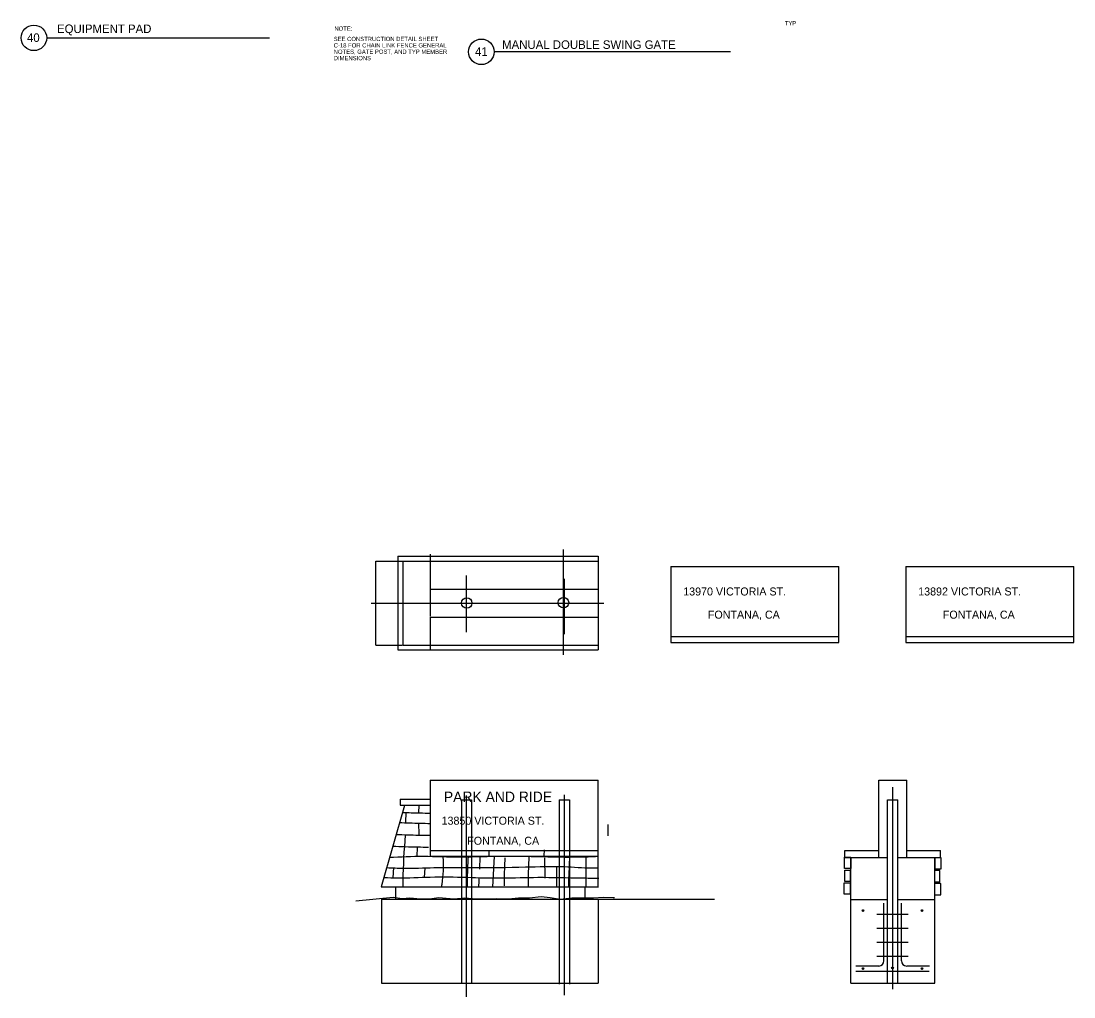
# Model space of a CAD drawing. Extents: x -121875 to -117742, y -103854 to -101122.
# Drawn here: x -121845 to -120364, y -103854 to -102481 of the extents above; entities that cross this region are included whole.
import ezdxf

# ---------------------------------------------------------------- set-up
doc = ezdxf.new("R2010")
doc.units = 0
doc.layers.add('49 Planting', color=7, linetype='Continuous')
doc.layers.add('Misc CnstDet(22)', color=7, linetype='Continuous')

msp = doc.modelspace()

# ---------------------------------------------------------------- linework, layer by layer
at = {"layer": '49 Planting'}
for p, q in [((-121081.8, -103372.5), (-121081.8, -103224.1)), ((-121346, -103358.7), (-121346, -103240.5)), ((-121346, -103240.5), (-121308.4, -103240.5)), ((-121315.3, -103233.6), (-121033.2, -103233.6)), ((-121315.3, -103233.6), (-121315.3, -103365.5)), ((-121307.9, -103240.5), (-121307.9, -103358.7)), ((-121307.9, -103240.5), (-121269.3, -103240.5)), ((-121269.6, -103231.1), (-121269.6, -103279.2)), ((-121269.6, -103234), (-121269.6, -103239.9)), ((-121269.3, -103240.5), (-121032.9, -103240.5)), ((-121033.2, -103233.6), (-121033.2, -103365.5)), ((-120930.9, -103248.1), (-120930.9, -103355)), ((-120930.9, -103248.1), (-120694.5, -103248.1)), ((-120694.5, -103355), (-120694.5, -103248.1)), ((-120600.2, -103248.1), (-120600.2, -103355)), ((-120600.2, -103248.1), (-120363.8, -103248.1)), ((-120363.8, -103355), (-120363.8, -103248.1)), ((-121218.9, -103261.1), (-121218.9, -103340.6)), ((-121081, -103265.6), (-121081, -103343.4)), ((-121270, -103279.9), (-121033.3, -103279.9)), ((-121269.6, -103279.8), (-121269.6, -103317.9)), ((-121352.9, -103299.6), (-121025, -103299.6)), ((-121269.6, -103319.1), (-121269.6, -103359)), ((-121269.3, -103319.3), (-121033.7, -103319.3)), ((-121346, -103358.7), (-121308.9, -103358.7)), ((-121307.9, -103358.7), (-121269.6, -103358.7)), ((-121269.6, -103358.7), (-121033.8, -103358.7)), ((-121269.6, -103359), (-121269.6, -103365.5)), ((-120930.9, -103346.9), (-120930.9, -103355)), ((-120930.9, -103346.9), (-120694.3, -103346.9)), ((-120930.9, -103355), (-120694.5, -103355)), ((-120600.2, -103346.9), (-120600.2, -103355)), ((-120600.2, -103346.9), (-120363.6, -103346.9)), ((-120600.2, -103355), (-120363.8, -103355)), ((-121315.3, -103365.5), (-121033.2, -103365.5)), ((-121269.6, -103548.9), (-121269.6, -103655.8)), ((-121269.6, -103548.9), (-121033.2, -103548.9)), ((-121033.2, -103698.7), (-121033.2, -103548.9)), ((-120638.4, -103657.3), (-120638.4, -103548.9)), ((-120638.4, -103548.9), (-120599, -103548.9)), ((-120599, -103657), (-120599, -103548.9)), ((-120618.7, -103843), (-120618.7, -103558.6)), ((-121312, -103575.5), (-121270.2, -103575.5)), ((-121312, -103575.5), (-121312, -103584.2)), ((-121225.7, -103576.6), (-121225.7, -103833.9)), ((-121225.7, -103576.6), (-121211.5, -103576.6)), ((-121218.9, -103570.6), (-121218.9, -103853.8)), ((-121211.5, -103576.6), (-121211.5, -103834.8)), ((-121087.9, -103576.6), (-121087.9, -103835.7)), ((-121087.9, -103576.6), (-121073.7, -103576.6)), ((-121081, -103569.7), (-121081, -103851.1)), ((-121073.7, -103576.6), (-121073.7, -103835.7)), ((-120626.1, -103834.8), (-120626.1, -103576.6)), ((-120626.1, -103576.6), (-120611.3, -103576.6)), ((-120611.3, -103834.8), (-120611.3, -103576.6)), ((-121305.8, -103584.5), (-121338.7, -103698.7)), ((-121312, -103584.2), (-121270, -103584.2)), ((-121303.9, -103594.5), (-121304.5, -103607.8)), ((-121285.6, -103584.4), (-121286, -103594.1)), ((-121286.1, -103609.5), (-121285.7, -103625.4)), ((-121019.4, -103611.4), (-121019.4, -103627.3)), ((-121288, -103643.4), (-121288.6, -103655.9)), ((-121269.6, -103647.7), (-121269.6, -103655.8)), ((-121269.6, -103647.7), (-121033, -103647.7)), ((-121269.6, -103655.8), (-121033.2, -103655.8)), ((-121199.6, -103656.2), (-121200.4, -103673.9)), ((-121187.1, -103648.2), (-121187.3, -103655.7)), ((-121179.4, -103655.8), (-121181.8, -103699.3)), ((-121109.3, -103646.9), (-121109.6, -103655.2)), ((-120686, -103647.7), (-120638.6, -103647.7)), ((-120686, -103657.5), (-120686, -103647.7)), ((-120598.9, -103647.7), (-120551.4, -103647.7)), ((-120551.4, -103657.5), (-120551.4, -103647.7)), ((-121108.8, -103657.9), (-121108.4, -103686.7)), ((-121091.9, -103671.2), (-121091.9, -103699.5)), ((-120686, -103657.5), (-120638.2, -103657.5)), ((-120677.8, -103759.9), (-120677.8, -103657.5)), ((-120638.3, -103657.5), (-120626.6, -103657.5)), ((-120611.5, -103657.5), (-120598.9, -103657.5)), ((-120598.9, -103657.5), (-120551.4, -103657.5)), ((-120559.6, -103759.9), (-120559.6, -103657.5)), ((-121321.3, -103671.7), (-121322.3, -103686.3)), ((-121277.1, -103672.1), (-121277.9, -103685.8)), ((-121338.7, -103698.7), (-121032.8, -103698.7)), ((-121318.6, -103699.7), (-121318.6, -103716.6)), ((-121052.2, -103698.9), (-121052.2, -103716.3)), ((-121338.6, -103716.4), (-120869.7, -103716.4)), ((-121338.3, -103716.2), (-121338.3, -103834.6)), ((-121318.9, -103716.4), (-120890.2, -103716.4)), ((-121033.2, -103716.8), (-121033.2, -103834.6)), ((-120677.9, -103716.7), (-120626.2, -103716.7)), ((-120631, -103803), (-120631, -103721.7)), ((-120612, -103716.7), (-120561, -103716.7)), ((-120606.4, -103803), (-120606.4, -103721.7)), ((-120596.8, -103738), (-120641.1, -103738)), ((-120677.8, -103834.6), (-120677.8, -103759.9)), ((-120596.8, -103757.7), (-120641.1, -103757.7)), ((-120559.6, -103834.6), (-120559.6, -103759.9)), ((-120596.8, -103777.4), (-120641.1, -103777.4)), ((-120596.8, -103797.1), (-120641.1, -103797.1)), ((-120567.2, -103818), (-120670.6, -103818)), ((-120638.4, -103810.4), (-120670.4, -103810.4)), ((-120567, -103810.4), (-120599, -103810.4)), ((-121338.3, -103834.6), (-121033.2, -103834.6)), ((-120677.8, -103834.6), (-120559.6, -103834.6))]:
    msp.add_line(p, q, dxfattribs=at)
for points in [[(-120686.7, -103657.2), (-120677.8, -103657.2), (-120677.8, -103673.1), (-120686.7, -103673.1)], [(-120550.3, -103657.9), (-120559.2, -103657.9), (-120559.2, -103673.8), (-120550.3, -103673.8)], [(-120686, -103675.3), (-120678.6, -103675.3), (-120678.6, -103691.2), (-120686, -103691.2)], [(-120552.5, -103675.9), (-120559.9, -103675.9), (-120559.9, -103691.9), (-120552.5, -103691.9)], [(-120687.1, -103693.2), (-120678.5, -103693.2), (-120678.5, -103709.1), (-120687.1, -103709.1)], [(-120551, -103694.3), (-120559.7, -103694.3), (-120559.7, -103710.2), (-120551, -103710.2)]]:
    msp.add_lwpolyline(points, close=True, dxfattribs=at)
msp.add_lwpolyline([(-121374.5, -103718.7), (-121321.9, -103713.4), (-121309, -103715.2), (-121298.5, -103714.6), (-121283.2, -103715.8), (-121270.8, -103715.8), (-121257.3, -103714), (-121236.4, -103715.8), (-121221, -103714.6), (-121205, -103715.8), (-121191.4, -103715.8), (-121176.7, -103715.2), (-121159.4, -103715.8), (-121145.3, -103714.6), (-121129.9, -103714.6), (-121113.2, -103712.7), (-121100.9, -103714), (-121086.8, -103716.4), (-121070.2, -103714.6), (-121056, -103714.6), (-121040, -103714.6), (-121026.4, -103713.4), (-121012.3, -103714), (-121010, -103713.7)], dxfattribs=at)
for centre, radius in [((-121218.2, -103299.6), 7.39), ((-121082.1, -103299.1), 7.39), ((-120660.5, -103732.3), 1.26), ((-120660.5, -103732.3), 1.13), ((-120660.5, -103732.3), 1.01), ((-120660.5, -103732.3), 0.908), ((-120660.5, -103732.3), 0.756), ((-120660.5, -103732.3), 0.834), ((-120660.5, -103732.3), 0.646), ((-120660.5, -103732.3), 0.555), ((-120660.5, -103732.3), 0.452), ((-120660.5, -103732.3), 0.347), ((-120660.5, -103732.3), 0.226), ((-120660.5, -103732.3), 0.113), ((-120577.4, -103732.3), 1.26), ((-120577.4, -103732.3), 1.13), ((-120577.4, -103732.3), 1.01), ((-120577.4, -103732.3), 0.908), ((-120577.4, -103732.3), 0.756), ((-120577.4, -103732.3), 0.834), ((-120577.4, -103732.3), 0.646), ((-120577.4, -103732.3), 0.555), ((-120577.4, -103732.3), 0.452), ((-120577.4, -103732.3), 0.347), ((-120577.4, -103732.3), 0.226), ((-120577.4, -103732.3), 0.113), ((-120660.5, -103813.9), 1.26), ((-120660.5, -103813.9), 1.13), ((-120660.5, -103813.9), 1.01), ((-120660.5, -103813.9), 0.908), ((-120660.5, -103813.9), 0.834), ((-120660.5, -103813.9), 0.756), ((-120660.5, -103813.9), 0.646), ((-120660.5, -103813.9), 0.555), ((-120660.5, -103813.9), 0.452), ((-120660.5, -103813.9), 0.347), ((-120660.5, -103813.9), 0.226), ((-120660.5, -103813.9), 0.113), ((-120618.9, -103813), 1.26), ((-120618.9, -103813), 1.13), ((-120618.9, -103813), 1.01), ((-120618.9, -103813), 0.908), ((-120618.9, -103813), 0.834), ((-120618.9, -103813), 0.756), ((-120618.9, -103813), 0.646), ((-120618.9, -103813), 0.555), ((-120618.9, -103813), 0.452), ((-120618.9, -103813), 0.347), ((-120618.9, -103813), 0.226), ((-120618.9, -103813), 0.113), ((-120577.4, -103813.9), 1.26), ((-120577.4, -103813.9), 1.13), ((-120577.4, -103813.9), 1.01), ((-120577.4, -103813.9), 0.908), ((-120577.4, -103813.9), 0.834), ((-120577.4, -103813.9), 0.756), ((-120577.4, -103813.9), 0.646), ((-120577.4, -103813.9), 0.555), ((-120577.4, -103813.9), 0.452), ((-120577.4, -103813.9), 0.347), ((-120577.4, -103813.9), 0.226), ((-120577.4, -103813.9), 0.113)]:
    msp.add_circle(centre, radius, dxfattribs=at)
for centre, start, end in [((-120638.4, -103803), 270, 0), ((-120599, -103803), 180, 270)]:
    msp.add_arc(centre, 7.39, start, end, dxfattribs=at)
for points in [[(-121308.7, -103594.2), (-121284, -103594.9), (-121269.5, -103595.2)], [(-121313, -103608.5), (-121284, -103609.4), (-121269.5, -103609.7)], [(-121317.1, -103625.1), (-121286, -103626.1), (-121268.6, -103626.3)], [(-121304.7, -103626.4), (-121308, -103689.9), (-121307.9, -103699.9)], [(-121322.4, -103641.6), (-121286.9, -103642.8), (-121272, -103643)], [(-121327.3, -103657.2), (-121279.2, -103655.9), (-121227.1, -103656.8), (-121184.2, -103655.9), (-121119.3, -103656.3), (-121057.7, -103656.8), (-121037, -103656.1)], [(-121216.2, -103656.2), (-121217.7, -103691.3), (-121217.8, -103699)], [(-121073.4, -103655.8), (-121074.9, -103691.3), (-121075.1, -103698.8)], [(-121033.4, -103672.8), (-121042.1, -103672.8), (-121080.9, -103670.9), (-121135.3, -103671.4), (-121210.4, -103672.2), (-121264.5, -103672.3), (-121307.5, -103673.2), (-121330.6, -103672.3)], [(-121251.6, -103656.9), (-121253.2, -103695.4), (-121253.8, -103699)], [(-121164.4, -103658), (-121165.7, -103689.9), (-121165.7, -103697.5)], [(-121130.7, -103656.8), (-121131.9, -103689.9), (-121131.9, -103698.9)], [(-121050.7, -103657.5), (-121050.4, -103691.3), (-121050.5, -103698.8)], [(-121032.5, -103687), (-121056.3, -103686.9), (-121118.1, -103686), (-121168.2, -103686.9), (-121218.2, -103686), (-121269.6, -103685.6), (-121315.4, -103686.9), (-121334.6, -103686.2)], [(-121201, -103686.8), (-121201.1, -103689.4), (-121201.5, -103698.3)]]:
    msp.add_spline(points, degree=3, dxfattribs=at)
at = {"layer": 'Misc CnstDet(22)'}
for p, q in [((-121809.4, -102504.5), (-121496, -102504.5)), ((-120847.1, -102524.1), (-121179.6, -102524.1))]:
    msp.add_line(p, q, dxfattribs=at)
for centre in [(-121827.4, -102504.5), (-121197.6, -102524.1)]:
    msp.add_circle(centre, 18, dxfattribs=at)

# ---------------------------------------------------------------- texts
at = {"layer": '49 Planting'}
for s, height, p in [('13970 VICTORIA ST.', 11.261, (-120913.5, -103289)), ('13892 VICTORIA ST.', 11.261, (-120582.8, -103289)), ('FONTANA, CA', 11.261, (-120878.8, -103321.6)), ('FONTANA, CA', 11.261, (-120548.1, -103321.6)), ('PARK AND RIDE', 14.64, (-121250.4, -103579.6)), ('13850 VICTORIA ST.', 11.261, (-121253.6, -103611.5)), ('FONTANA, CA', 11.261, (-121217.5, -103639.7))]:
    msp.add_text(s, height=height, dxfattribs=at).set_placement(p)
at = {"layer": 'Misc CnstDet(22)'}
for s, height, p in [('EQUIPMENT PAD', 12, (-121794.8, -102497.7)), ('TYP', 6, (-120770.5, -102486.9)), ('40', 12, (-121837.1, -102510.2)), ('NOTE:', 6, (-121404.4, -102494.5)), ('SEE CONSTRUCTION DETAIL SHEET', 6, (-121405.4, -102509)), ('C-18 FOR CHAIN LINK FENCE GENERAL', 6, (-121405.4, -102518)), ('MANUAL DOUBLE SWING GATE', 12, (-121168.4, -102520)), ('NOTES, GATE POST, AND TYP MEMBER', 6, (-121405.4, -102527)), ('DIMENSIONS', 6, (-121405.4, -102536)), ('41', 12, (-121206.5, -102529.8))]:
    msp.add_text(s, height=height, dxfattribs=at).set_placement(p)

doc.saveas('drawing.dxf')
